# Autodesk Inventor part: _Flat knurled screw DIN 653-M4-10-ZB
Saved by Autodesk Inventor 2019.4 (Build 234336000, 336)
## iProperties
Created: 2021-06
Part Number: _Flat knurled screw DIN 653-M4-10-ZB
Material: Generic
Document SubType Name: Modeling
Designer: Administrator
Density: 1 g/cm^3
Appearance: Default
Title: _Flat knurled screw DIN 653-M4-10-ZB
Author: Administrator
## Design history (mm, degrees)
feature "Body1"
body "Solid1"
